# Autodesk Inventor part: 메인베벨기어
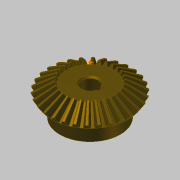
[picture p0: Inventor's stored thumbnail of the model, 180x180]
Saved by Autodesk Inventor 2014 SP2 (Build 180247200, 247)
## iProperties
Created: 2018-09
Part Number: 메인베벨기어
Material: 강철, 탄소
Document SubType Name: Modeling
Categories: <?xml version="1.0" encoding="UTF-16"?> <MemberInstance><Categories><FamilyTemplate><FamilyTemplateParameter ValueType="xs:double" Id="1" ObjectReferenceKey="da
Mass: 290.333 g
Surface Area: 107.716 cm^2
Volume: 36.8911 cm^3
Density: 7.87 g/cm^3
Appearance: 얼룩무늬
CustomPartVersion: 1
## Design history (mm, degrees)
node "맨 위 점"
node "메쉬 평면2"
sketch "톱니 본체 스케치"
  geometry: L1 (0, 0)-(28.669, -21.997); L2 (28.669, -21.997)-(31.109, -18.336); L3 (31.109, -18.336)-(0, 0); L4 (30, -20)-(0, 0); L5 (17.219, -13.212)-(18.685, -11.013); L6 (28.669, -21.997)-(17.219, -13.212); L7 (31.109, -18.336)-(18.685, -11.013); L8 (0, -39.387)-(0, 6.564) reference; L9 (0, -20)-(31.109, -20)
  constraints: 16 end point, 4 point on line, 3 perpendicular, 2 collinear, 1 horizontal alignment, 1 vertical alignment
  dimensions: "d0" = 60 diameter of L4.start L8 (= da_de); "d1" = 57.33744 diameter of L1.end L8 (= da_dfe); "d2" = 62.2188 diameter of L2.end L8 (= da_dae); "d3" = 14.4 distance between parallel lines of L2 L5 (= da_b); "d4" = 18.3359 vertical distance of L2.end L1.start (= da_ve)
revolve "톱니 본체" sketch "톱니 본체 스케치" stored, may be unused: angle "d5" = 90 deg
node "시작점"
node "톱니 평면"
sketch "시작 스케치"
  geometry: L1 (0, -23.505)-(0, 10.645) reference; L2 (-0.709, -2.928)-(0.709, -2.928); A1 r 19.188 centre (-19.457, -7.014) between (-0.709, -2.928) and (-3.232, 3.229); A2 r 19.188 centre (19.457, -7.014) between (3.232, 3.229) and (0.709, -2.928); A3 r 57.403 centre (0, -54.083) between (3.232, 3.229) and (-3.232, 3.229); 1 further point
  constraints: 6 point on circle, 3 centre point, 3 symmetric about line, 2 end point, 1 coincident, 1 perpendicular, 1 other
  dimensions: "d7" = 19.18795 radius of A1 (= fd_rr); "d8" = 19.45712 horizontal distance of point (0, -54.083) A1.centre (= fd_x); "d9" = 47.06905 vertical distance of point (0, -54.083) A1.centre (= fd_y); "d57" = 57.40327 radius of A3 (= 0.5 x fd_dva + 0.3 x da_he); "d58" = 51.15527 distance from line of A3.centre L2 (= 0.5 x fd_dva - 1.12 x da_he)
node "끝점"
  node "끝 평면"
sketch "3D 스케치 오른쪽"
  node "Helical Curve Right" dims "d65" = 229.90621 (computed from da_dm, da_delta, da_beta), "d66" = 31.5, "d67" = 60 (= da_de), "d68" = -9.82794 (= -da_delta), "d69" = 8.10972 (computed from fd_loft, da_delta)
node "끝 평면 오른쪽"
sketch "끝 스케치 오른쪽"
  geometry: L1 (0, -41.54)-(0, 13.178) reference; L2 (-0.422, -1.69)-(0.422, -1.69); A1 r 11.427 centre (-11.587, -4.123) between (-0.422, -1.69) and (-1.925, 1.977); A2 r 11.427 centre (11.587, -4.123) between (1.925, 1.977) and (0.422, -1.69); A3 r 34.184 centre (0, -32.153) between (1.925, 1.977) and (-1.925, 1.977); 1 further point
  constraints: 6 point on circle, 3 centre point, 3 symmetric about line, 2 end point, 1 coincident, 1 perpendicular, 1 other
  dimensions: "d70" = 11.58699 horizontal distance of A3.centre A1.centre (computed from fd_x, fd_ratio); "d71" = 28.03028 vertical distance of point (0, -32.153) A1.centre (computed from fd_y, fd_ratio); "d72" = 11.4267 radius of A1 (computed from fd_rr, fd_ratio); "d73" = 30.46369 distance from line of point (0, -32.153) L2 (computed from d58, fd_ratio); "d74" = 34.18446 radius of A3 (computed from d57, fd_ratio)
feature "로프트 오른쪽" sketch "끝 스케치 오른쪽" dims "d75" = 0, "d77" = 0, "d79" = 0, "d80" = 90 deg, "d85" = 20, "d92" = 90 deg, "d93" = 90 deg, "da_teethtype" = 0 [user parameter]
sketch "3D 스케치 왼쪽"
  node "Helical Curve Left" dims "d26" = 229.90621 (computed from da_dm, da_delta, da_beta), "d27" = 8.10972 (computed from fd_loft, da_delta), "d28" = 60 (= da_de), "d29" = -9.82794 (= -da_delta)
node "끝 평면 왼쪽"
sketch "끝 스케치 왼쪽" dims "d56" = 10.3728 (derived)
  geometry: L1 (0, -43.753)-(0, 15.405) reference; L2 (-0.422, -1.678)-(0.422, -1.678); A1 r 11.427 centre (-11.587, -4.111) between (-0.422, -1.678) and (-1.925, 1.988); A2 r 11.427 centre (11.587, -4.111) between (1.925, 1.988) and (0.422, -1.678); A3 r 34.184 centre (0, -32.142) between (1.925, 1.988) and (-1.925, 1.988); 2 further points; 1 other entity
  constraints: 6 point on circle, 3 centre point, 3 symmetric about line, 2 end point, 1 coincident, 2 other
  dimensions: "d30" = 11.4267 radius of A1 (computed from fd_rr, fd_ratio); "d31" = 11.58699 horizontal distance of point (0, -32.142) A1.centre (computed from fd_x, fd_ratio); "d32" = 28.03028 vertical distance of A1.centre point (0, -32.142) (computed from fd_y, fd_ratio); "d61" = 34.18446 radius of A3 (computed from d57, fd_ratio); "d62" = 30.46369 distance from line of point (0, -32.142) L2 (computed from d58, fd_ratio)
feature "로프트 왼쪽" sketch "끝 스케치 왼쪽" dims "d35" = 0, "d37" = 0, "d39" = 0, "d40" = 90 deg, "d84" = 10, "d90" = 90 deg, "d91" = 90 deg, "da_teethtype" = 0 [user parameter]
sketch "본체 스케치"
  geometry: L1 (0, -35.038)-(0, -19.531) reference; L2 (28.669, -21.997)-(17.219, -13.212) reference; L3 (17.219, -13.212)-(0, -13.212); L4 (28.669, -21.997)-(0, -21.997)
  constraints: 4 end point, 2 perpendicular, 2 point on line
revolve "본체 고정" sketch "본체 스케치" stored, may be unused: angle "d46" = 90 deg
feature "피치 지름" dims angle "d47" = 90 deg
sketch "스케치8"
  geometry: C1 r 22.5 at (0, 0); 1 further point
  constraints: 1 centre point, 1 coincident
  dimensions: "d94" = 45 diameter of C1
extrude "돌출1" join sketch "스케치8" distance "d95" = 13; taper "d96" = 0 deg
sketch "스케치9"
  geometry: 1 further point
hole "구멍1" sketch "스케치9" at (0, 0) diameter "d97" = 12; stored, may be unused: countersink angle "d101" = 90 deg, drill point angle "d103" = 118 deg; dims "d98" = 6, "d99" = 4, "d100" = 2, "d102" = 8
sketch "스케치10"
  geometry: L1 (5.657, 2)-(7.8, 2); L2 (7.8, 2)-(7.8, -2); L3 (7.8, -2)-(5.657, -2); A1 r 6 centre (0, 0) between (5.657, 2) and (5.657, -2) reference; 1 further point
  constraints: 6 end point, 2 parallel, 2 point on circle, 1 horizontal, 1 perpendicular
  dimensions: "d104" = 4 distance of L1.end L2.end; "d112" = 13.8 dimension on A1 L2
extrude "돌출2" cut sketch "스케치10" stored distance "d106" = 10; taper "d107" = 0 deg
chamfer "모따기1" distance "d108" = 1; stored, may be unused: second distance "d109" = 2, angle "d110" = 45 deg
fillet "모깎기1" dims "d111" = 2
body "Solid1"
feature "로프트" dims "d17" = 0, "d18" = 90 deg, "d19" = 0, "d20" = 90 deg, "d89" = 0, "da_teethtype" = 0 [user parameter]
pattern_circular "원형 패턴" dims angle "d22" = 360 deg, "d88" = 0, "da_teethtype" = 0 [user parameter]
pattern_circular "원형 패턴 오른쪽" dims angle "d82" = 360 deg, "da_teethtype" = 0 [user parameter]
pattern_circular "원형 패턴 왼쪽" dims angle "d42" = 360 deg, "da_teethtype" = 0 [user parameter]
sketch "끝 스케치"
  geometry: L1 (0, -15.359)-(0, 6.983) reference; L2 (-0.422, -1.69)-(0.422, -1.69); A1 r 11.427 centre (-11.587, -4.123) between (-0.422, -1.69) and (-1.925, 1.977); A2 r 11.427 centre (11.587, -4.123) between (1.925, 1.977) and (0.422, -1.69); A3 r 34.184 centre (0, -32.153) between (1.925, 1.977) and (-1.925, 1.977); 1 further point
  constraints: 6 point on circle, 3 centre point, 3 symmetric about line, 2 end point, 1 coincident, 1 other
  dimensions: "d12" = 11.4267 radius of A1 (computed from fd_rr, fd_ratio); "d15" = 11.58699 horizontal distance of A1.centre point (0, -32.153) (computed from fd_x, fd_ratio); "d16" = 28.03028 vertical distance of A1.centre point (0, -32.153) (computed from fd_y, fd_ratio); "d59" = 34.18446 radius of A3 (computed from d57, fd_ratio); "d60" = 30.46369 distance from line of A3.centre L2 (computed from d58, fd_ratio)
sketch "Sketch6"
  geometry: L1 (30, -20)-(0, 0) reference; L2 (0, -37.8)-(0, 6.3) reference
body "Srf1"
other parameters: "da_b" = 14.4 [user parameter; used in 2 equation terms], "da_de" = 60 [user parameter; used in 4 equation terms], "da_dae" = 62.2188 [user parameter; used in 2 equation terms], "da_dfe" = 57.33744 [user parameter; used in 1 equation term], "da_le" = 36.05551 [user parameter; used in 1 equation term], "da_omega" = 90 deg [user parameter; used in 1 equation term], "da_beta" = 0 [user parameter; used in 2 equation terms], "da_delta" = 9.82794 [user parameter; used in 8 equation terms], "da_alpha" = 20 deg [user parameter; used in 2 equation terms], "da_he" = 4.4 [user parameter; used in 4 equation terms], "da_ve" = 18.3359 [user parameter; used in 1 equation term], "fd_dv" = 108.16654 (computed from da_de, da_delta) [user parameter; used in 1 equation term], "fd_dva" = 112.16654 (computed from da_dae, da_delta) [user parameter; used in 3 equation terms], "fd_dvb" = 101.6433 (computed from fd_dv, da_alpha) [user parameter; used in 2 equation terms], "da_zv" = 540.83269 [user parameter; used in 1 equation term], "fd_loft" = 14.62 (= da_b + 0.05 x da_he) [user parameter; used in 4 equation terms], "fd_ratio" = 5.95514 (computed from da_le, fd_loft) [user parameter; used in 15 equation terms], "fd_rr" = 19.18795 (computed from fd_dd, fd_dvb) [user parameter; used in 6 equation terms], "fd_angle" = 0.29367 (computed from da_zv) [user parameter; used in 4 equation terms], "fd_x1" = 1.58802 (computed from da_dvw, fd_angle) [user parameter; used in 1 equation term], "fd_y1" = 54.05995 (computed from da_dvw, fd_angle) [user parameter; used in 1 equation term], "fd_x2" = 17.8691 (computed from fd_rr, fd_angle2, fd_angle) [user parameter; used in 1 equation term], "fd_y2" = 6.9909 (computed from fd_rr, fd_angle2, fd_angle) [user parameter; used in 1 equation term], "fd_x" = 19.45712 (= fd_x1 + fd_x2) [user parameter; used in 4 equation terms], "fd_y" = 47.06905 (= fd_y1 - fd_y2) [user parameter; used in 4 equation terms], "fd_angle2" = 3.43555 (computed from fd_dvb, fd_dd, da_alpha) [user parameter; used in 2 equation terms], "fd_dd" = 108.64654 (= fd_dva - 0.8 x da_he) [user parameter; used in 2 equation terms], "da_dvw" = 108.16654 [user parameter; used in 2 equation terms], "d11" = 14.62 (= fd_loft), "da_dm" = 48.01848 [user parameter; used in 2 equation terms], "da_x" = 0 [user parameter], "da_m" = 2 [user parameter], "d48" = 0, "d49" = 0, "d50" = 90 deg (= da_omega), "d51" = 6 deg (computed from da_z), "d52" = 0, "d53" = 0, "d54" = 0
